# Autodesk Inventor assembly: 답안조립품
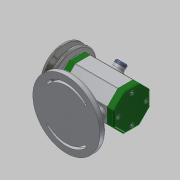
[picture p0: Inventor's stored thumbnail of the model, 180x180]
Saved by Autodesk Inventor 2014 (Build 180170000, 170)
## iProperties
Created: 2017-06
Part Number: 답안조립품
Document SubType Name: Assembly
Designer: Administrator
Author: Administrator
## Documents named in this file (14)
- C:\Users\Administrator\Desktop\470608V1004\답안조립품.iam
- C:\Users\Administrator\Desktop\470608V1004\1-본체.ipt
- C:\Users\Administrator\Desktop\470608V1004\V벨트풀리.ipt
- C:\Users\Administrator\Desktop\470608V1004\고무캡.ipt
- C:\Users\Administrator\Desktop\470608V1004\너트 M 8.ipt
- C:\Users\Administrator\Desktop\470608V1004\뒤커버.ipt
- C:\Users\Administrator\Desktop\470608V1004\베어링 15 x 32 x 9.ipt
- C:\Users\Administrator\Desktop\470608V1004\볼트 M4 x 12.ipt
- C:\Users\Administrator\Desktop\470608V1004\스프링와셔 8.ipt
- C:\Users\Administrator\Desktop\470608V1004\앞커버.ipt
- C:\Users\Administrator\Desktop\470608V1004\오일 실 15 25 7.ipt
- C:\Users\Administrator\Desktop\470608V1004\와셔 8x17.ipt
- C:\Users\Administrator\Desktop\470608V1004\축.ipt
- C:\Users\Administrator\Desktop\470608V1004\키 3 x 3 x 12.ipt
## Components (3 placed, 3 different names)
1. 1-본체:1 — Mate:8, Mate:9, Mate:10, Mate:11, Mate:12, Mate:13, Mate:17, Mate:29, Mate:30, Mate:31, Mate:32
2. V벨트풀리:1 — Mate:19, Angle:1, Mate:20, Mate:22
3. 고무캡:1 — Mate:29, Mate:30
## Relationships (15: Mate 14, Angle 1)
- Mate:8: 1-본체:1
- Mate:9: 1-본체:1
- Mate:10: 1-본체:1
- Mate:11: 1-본체:1
- Mate:12: 1-본체:1
- Mate:13: 1-본체:1
- Mate:17: 1-본체:1
- Mate:19: V벨트풀리:1
- Angle:1: V벨트풀리:1
- Mate:20: V벨트풀리:1
- Mate:22: V벨트풀리:1
- Mate:29: 1-본체:1 ↔ 고무캡:1
- Mate:30: 1-본체:1 ↔ 고무캡:1
- Mate:31: 1-본체:1
- Mate:32: 1-본체:1
